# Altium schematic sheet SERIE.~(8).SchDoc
size A4
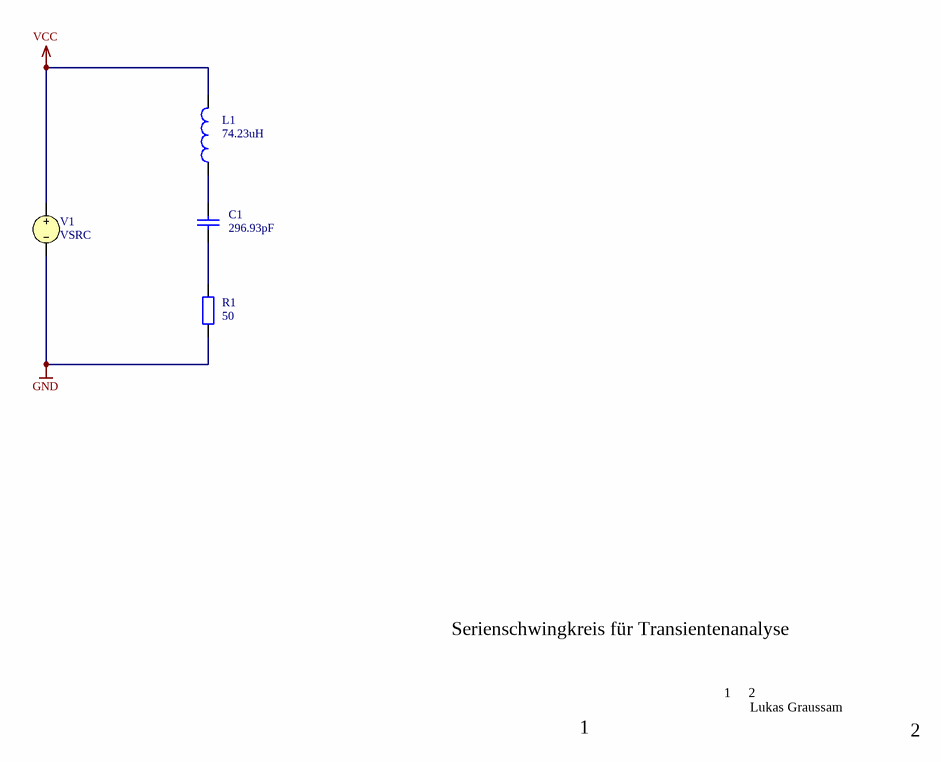
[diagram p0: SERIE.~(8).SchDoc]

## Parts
C1  value 296.93pF  [RAD-0.3]  (hidden comment: Cap)
L1  value 74.23uH  [0402-A]  (hidden comment: Inductor)
R1  value 50  [AXIAL-0.4]  (hidden comment: Res2)
V1  VSRC

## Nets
GND: R1.1 V1.2
VCC: L1.2 V1.1
NetC1_1: C1.1 L1.1
NetC1_2: C1.2 R1.2

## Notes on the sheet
- Serienschwingkreis für Transientenanalyse
- 1
- 2
- Lukas Graussam

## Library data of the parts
C1 = Cap: Capacitor
L1 = Inductor: Code_IEC: 1005
R1 = Res2: Resistor
V1 = VSRC: Voltage Source; Note: PCB Footprint - Not required; Value: 10mV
